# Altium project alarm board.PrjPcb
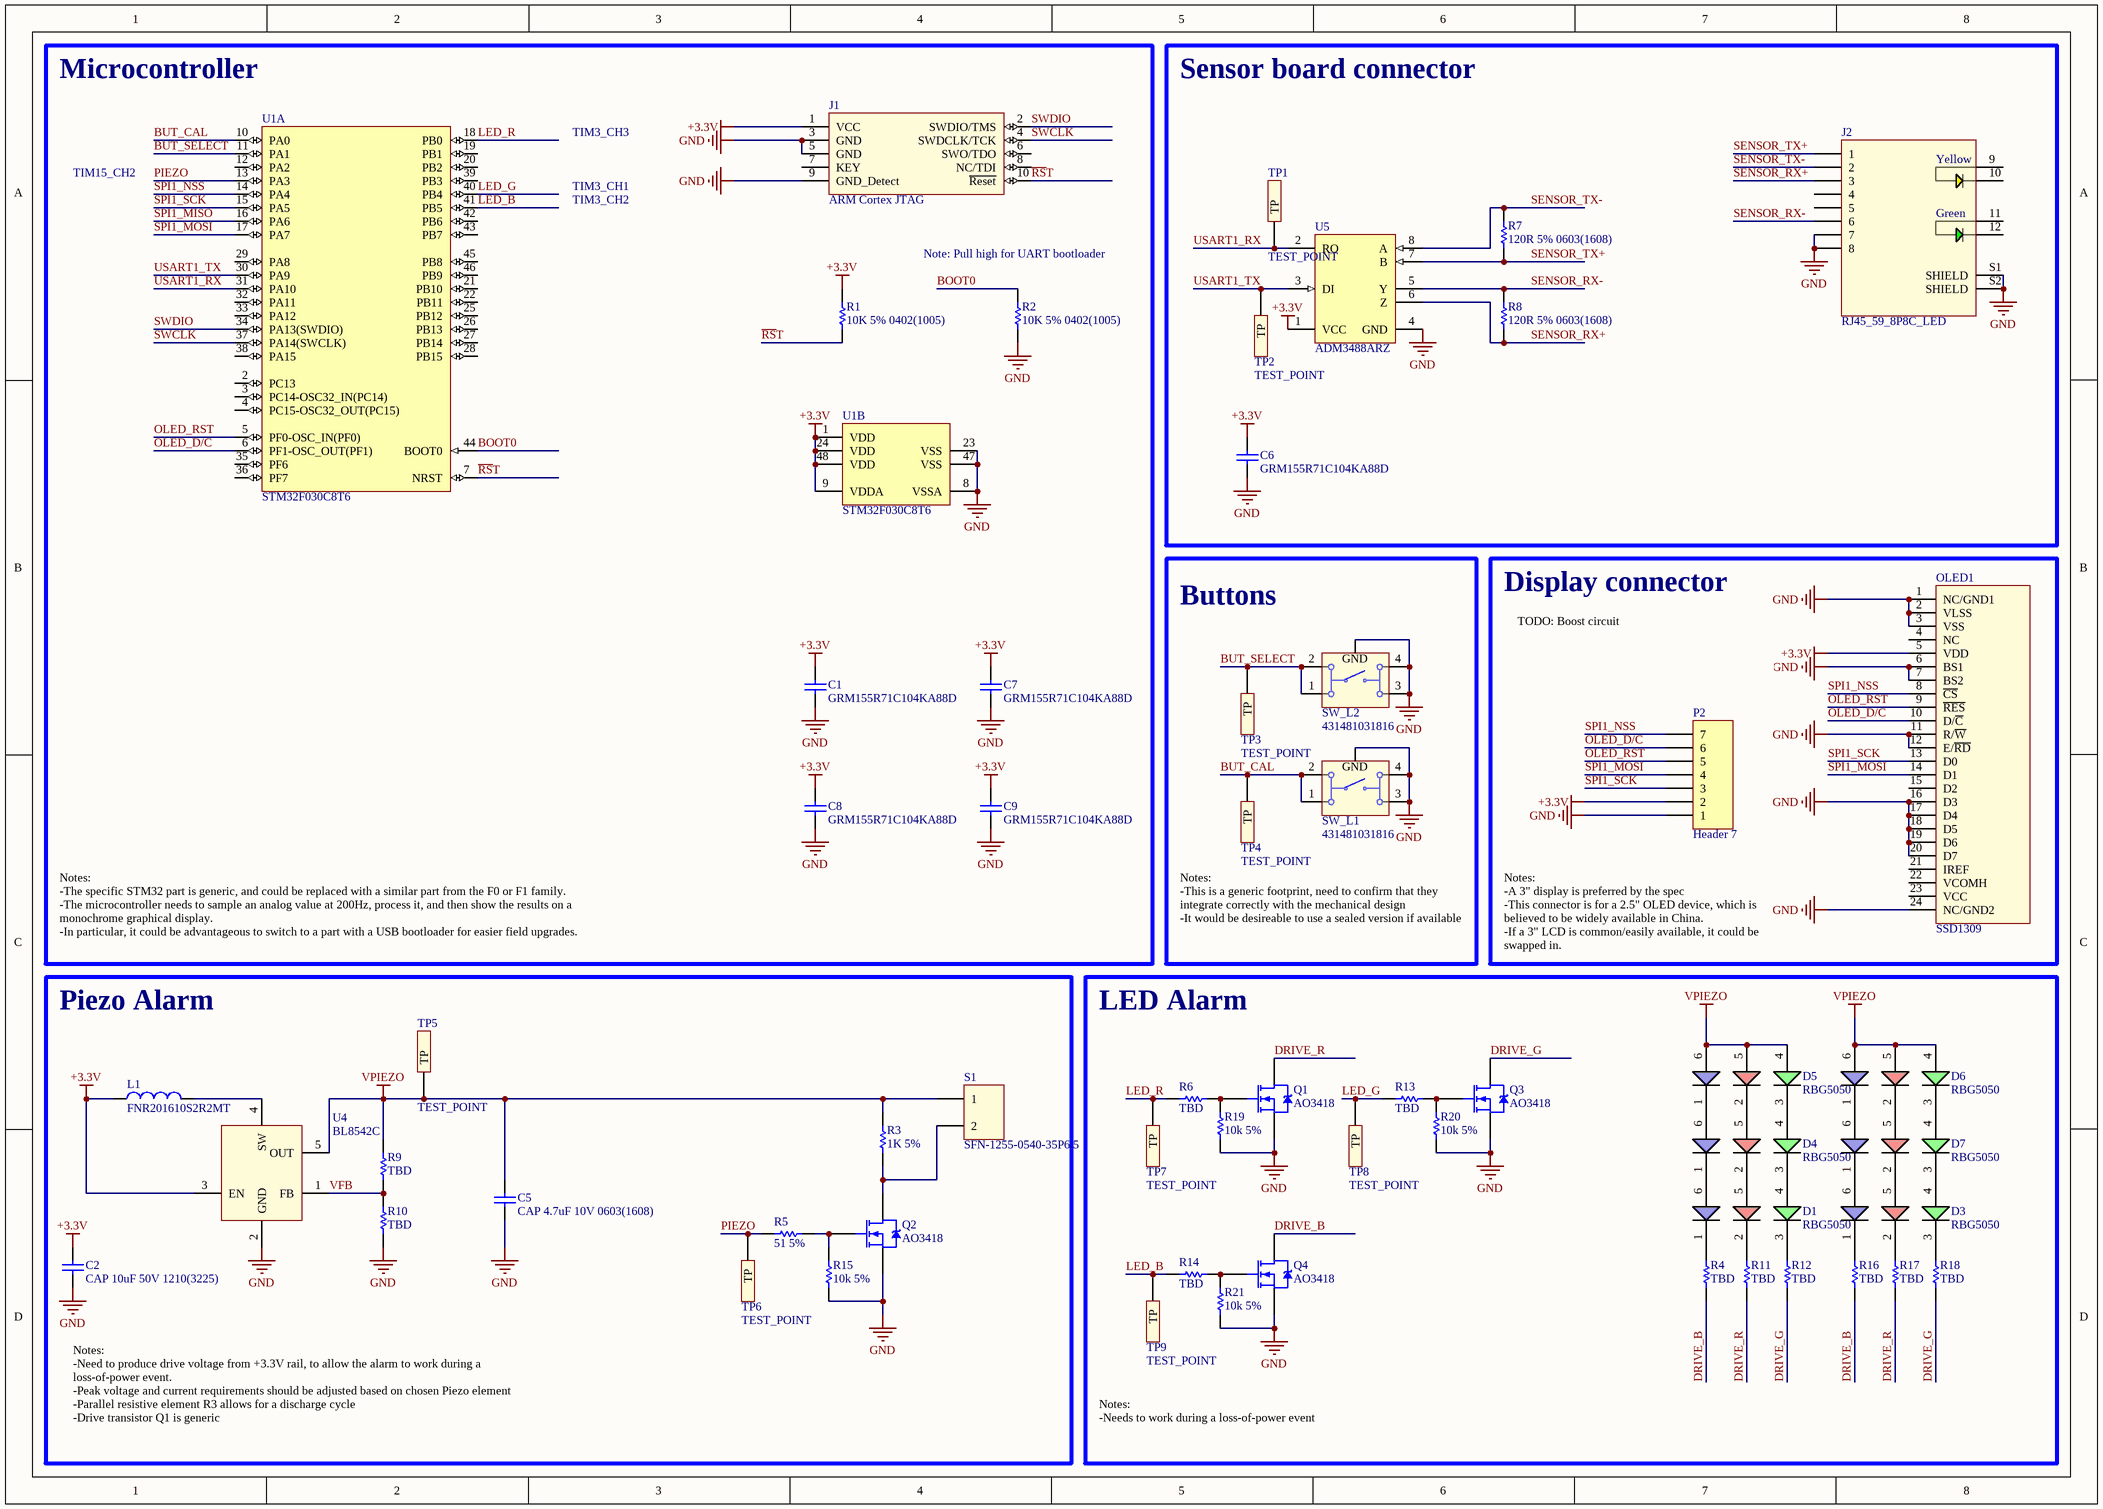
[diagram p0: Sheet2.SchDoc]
2 sheets, 68 parts. Net scope: global (net labels, ports and power ports of the same name join across sheets).
Board file: PCB2.PcbDoc
Sheets:
  Sheet2.SchDoc
  power.SchDoc

## Sheet Sheet2.SchDoc: Alarm Board
size A3

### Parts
C1  GRM155R71C104KA88D  [CAPC1005X55X25ML05T10]
C2  CAP 10uF 50V 1210(3225)  [CAPC1210(3225)190_N]
C5  CAP 4.7uF 10V 0603(1608)  [CAPC0603(1608)55_L]
C6  GRM155R71C104KA88D  [CAPC1005X55X25ML05T10]
C7  GRM155R71C104KA88D  [CAPC1005X55X25ML05T10]
C8  GRM155R71C104KA88D  [CAPC1005X55X25ML05T10]
C9  GRM155R71C104KA88D  [CAPC1005X55X25ML05T10]
D1  RBG5050  [5050RGB]
D3  RBG5050  [5050RGB]
D4  RBG5050  [5050RGB]
D5  RBG5050  [5050RGB]
D6  RBG5050  [5050RGB]
D7  RBG5050  [5050RGB]
J1  ARM Cortex JTAG  [1.27mm 2x5 SMD Header]
J2  RJ45_59_8P8C_LED  [RJ45_59_8P8C_LED]
L1  FNR201610S2R2MT  [FNR201610S]
OLED1  SSD1309
P2  Header 7  [HDR1X7]
Q1  AO3418  [SOT95P280X125-3N]
Q2  AO3418  [SOT95P280X125-3N]
Q3  AO3418  [SOT95P280X125-3N]
Q4  AO3418  [SOT95P280X125-3N]
R1  10K 5% 0402(1005)  [RESC0402(1005)_N]
R2  10K 5% 0402(1005)  [RESC0402(1005)_N]
R3  1K 5%  [RESC0402(1005)_N]
R4  TBD  [RESC0402(1005)_N]
R5  51 5%  [RESC0402(1005)_N]
R6  TBD  [RESC0402(1005)_N]
R7  120R 5% 0603(1608)  [RESC0603(1608)_L]
R8  120R 5% 0603(1608)  [RESC0603(1608)_L]
R9  TBD  [RESC0402(1005)_N]
R10  TBD  [RESC0402(1005)_N]
R11  TBD  [RESC0402(1005)_N]
R12  TBD  [RESC0402(1005)_N]
R13  TBD  [RESC0402(1005)_N]
R14  TBD  [RESC0402(1005)_N]
R15  10k 5%  [RESC0402(1005)_N]
R16  TBD  [RESC0402(1005)_N]
R17  TBD  [RESC0402(1005)_N]
R18  TBD  [RESC0402(1005)_N]
R19  10k 5%  [RESC0402(1005)_N]
R20  10k 5%  [RESC0402(1005)_N]
R21  10k 5%  [RESC0402(1005)_N]
S1  SFN-1255-0540-35P6.5  [SFN-1255-0540-35P6.5]
SW_L1  431481031816  [431481031816]
SW_L2  431481031816  [431481031816]
TP1  TEST_POINT  [TP-SMD-1mm]  (no BOM)
TP2  TEST_POINT  [TP-SMD-1mm]  (no BOM)
TP3  TEST_POINT  [TP-SMD-1mm]  (no BOM)
TP4  TEST_POINT  [TP-SMD-1mm]  (no BOM)
TP5  TEST_POINT  [TP-SMD-1mm]  (no BOM)
TP6  TEST_POINT  [TP-SMD-1mm]  (no BOM)
TP7  TEST_POINT  [TP-SMD-1mm]  (no BOM)
TP8  TEST_POINT  [TP-SMD-1mm]  (no BOM)
TP9  TEST_POINT  [TP-SMD-1mm]  (no BOM)
U1  STM32F030C8T6  [STM-LQFP48_M]  (parts A,B of 2)
U4  BL8542C  [SOT95P280X130-5N]
U5  ADM3488ARZ  [ADI-R-8_L]

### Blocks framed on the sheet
Microcontroller: C1 C7-C9 J1 R1 R2 U1
Sensor board connector: C6 J2 R7 R8 TP1 TP2 U5
Buttons: SW_L1 SW_L2 TP3 TP4
Display connector: OLED1 P2
Piezo Alarm: C2 C5 L1 Q2 R3 R5 R9 R10 R15 S1 TP5 TP6 U4
LED Alarm: D1 D3-D7 Q1 Q3 Q4 R4 R6 R11-R14 R16-R21 TP7-TP9

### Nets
+3.3V: C1.2 C2.2 C6.2 C7.2 C8.2 C9.2 J1.1(VCC) L1.1 OLED1.5(VDD) P2.2 R1.1 U1.1(VDD) U1.9(VDDA) U1.24(VDD) U1.48(VDD) U4.3(EN) U5.1(VCC)
GND: C1.1 C2.1 C5.1 C6.1 C7.1 C8.1 C9.1 J1.3(GND) J1.5(GND) J1.9(GND_Detect) J2.7 J2.8 J2.S1(SHIELD) J2.S2(SHIELD) OLED1.1(NC/GND1) OLED1.2(VLSS) OLED1.3(VSS) OLED1.6(BS1) OLED1.7(BS2) OLED1.11(R/~{W}) OLED1.12(E/~{RD}) OLED1.16(D3) OLED1.17(D4) OLED1.18(D5) OLED1.19(D6) OLED1.20(D7) OLED1.24(NC/GND2) P2.1 Q1.2(SOURCE) Q2.2(SOURCE) Q3.2(SOURCE) Q4.2(SOURCE) R2.2 R10.1 R15.1 R19.1 R20.1 R21.1 SW_L1.3 SW_L1.4 SW_L1.5 SW_L2.3 SW_L2.4 SW_L2.5 U1.8(VSSA) U1.23(VSS) U1.47(VSS) U4.2(GND) U5.4(GND)
VPIEZO: C5.2 D5.4 D5.5 D5.6 D6.4 D6.5 D6.6 R3.2 R9.2 S1.1 TP5.1(TP) U4.5(OUT)
~{RS}T: J1.10(~{Reset}) R1.2 U1.7(NRST)
BOOT0: R2.1 U1.44(BOOT0)
BUT_CAL: SW_L1.1 SW_L1.2 TP4.1(TP) U1.10(PA0)
BUT_SELECT: SW_L2.1 SW_L2.2 TP3.1(TP) U1.11(PA1)
DRIVE_B: Q4.3(DRAIN) R4.1 R16.1
DRIVE_G: Q3.3(DRAIN) R12.1 R18.1
DRIVE_R: Q1.3(DRAIN) R11.1 R17.1
LED_B: R14.1 TP9.1(TP) U1.41(PB5)
LED_G: R13.1 TP8.1(TP) U1.40(PB4)
LED_R: R6.1 TP7.1(TP) U1.18(PB0)
OLED_D/C: OLED1.10(D/~{C}) P2.6 U1.6(PF1-OSC_OUT(PF1))
OLED_RST: OLED1.9(~{RES}) P2.5 U1.5(PF0-OSC_IN(PF0))
PIEZO: R5.1 TP6.1(TP) U1.13(PA3)
SENSOR_RX+: J2.3 R8.1 U5.6(Z)
SENSOR_RX-: J2.6 R8.2 U5.5(Y)
SENSOR_TX+: J2.1 R7.1 U5.7(B)
SENSOR_TX-: J2.2 R7.2 U5.8(A)
SPI1_MISO: U1.16(PA6)
SPI1_MOSI: OLED1.14(D1) P2.4 U1.17(PA7)
SPI1_NSS: OLED1.8(~{CS}) P2.7 U1.14(PA4)
SPI1_SCK: OLED1.13(D0) P2.3 U1.15(PA5)
SWCLK: J1.4(SWDCLK/TCK) U1.37(PA14(SWCLK))
SWDIO: J1.2(SWDIO/TMS) U1.34(PA13(SWDIO))
USART1_RX: TP1.1(TP) U1.31(PA10) U5.2(RO)
USART1_TX: TP2.1(TP) U1.30(PA9) U5.3(DI)
VFB: R9.1 R10.2 U4.1(FB)
NetD1_1: D1.1 R4.2
NetD1_2: D1.2 R11.2
NetD1_3: D1.3 R12.2
NetD1_4: D1.4 D4.3
NetD1_5: D1.5 D4.2
NetD1_6: D1.6 D4.1
NetD3_1: D3.1 R16.2
NetD3_2: D3.2 R17.2
NetD3_3: D3.3 R18.2
NetD3_4: D3.4 D7.3
NetD3_5: D3.5 D7.2
NetD3_6: D3.6 D7.1
NetD4_4: D4.4 D5.3
NetD4_5: D4.5 D5.2
NetD4_6: D4.6 D5.1
NetD6_1: D6.1 D7.6
NetD6_2: D6.2 D7.5
NetD6_3: D6.3 D7.4
NetL1_2: L1.2 U4.4(SW)
NetQ1_1: Q1.1(GATE) R6.2 R19.2
NetQ2_1: Q2.1(GATE) R5.2 R15.2
NetQ2_3: Q2.3(DRAIN) R3.1 S1.2
NetQ3_1: Q3.1(GATE) R13.2 R20.2
NetQ4_1: Q4.1(GATE) R14.2 R21.2

Not connected (* = marked no-connect by the designer): J1 6(SWO/TDO) 7(KEY) 8(NC/TDI); J2 4 5 9(Yellow_Anode) 10(Yellow_Cathode) 11(Green_Anode) 12(Green_Cathode); OLED1 4(NC) 15(D2) 21(IREF) 22(VCOMH) 23(VCC); U1 2(PC13) 3(PC14-OSC32_IN(PC14)) 4(PC15-OSC32_OUT(PC15)) 12(PA2) 19(PB1) 20(PB2) 21(PB10) 22(PB11) 25(PB12) 26(PB13) 27(PB14) 28(PB15) 29(PA8) 32(PA11) 33(PA12) 35(PF6) 36(PF7) 38(PA15) 39(PB3) 42(PB6) 43(PB7) 45(PB8) 46(PB9)

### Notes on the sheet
- TIM15_CH2
- TIM3_CH3
- TIM3_CH1
- TIM3_CH2
- (near R2) Note: Pull high for UART bootloader
- (near P2) TODO: Boost circuit
- Notes:
  -The specific STM32 part is generic, and could be replaced with a similar part from the F0 or F1 family.
  -The microcontroller needs to sample an analog value at 200Hz, process it, and then show the results on a monochrome graphical display.
  -In particular, it could be advantageous to switch to a part with a USB bootloader for easier field upgrades.
- Notes:
  -This is a generic footprint, need to confirm that they integrate correctly with the mechanical design
  -It would be desireable to use a sealed version if available
- Notes:
  -A 3" display is preferred by the spec
  -This connector is for a 2.5" OLED device, which is believed to be widely available in China.
  -If a 3" LCD is common/easily available, it could be swapped in.
- Notes:
  -Need to produce drive voltage from +3.3V rail, to allow the alarm to work during a loss-of-power event.
  -Peak voltage and current requirements should be adjusted based on chosen Piezo element
  -Parallel resistive element R3 allows for a discharge cycle
  -Drive transistor Q1 is generic
- Notes:
  -Needs to work during a loss-of-power event

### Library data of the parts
C1 C6-C9 = CMP-2100-03641-1: Chip Capacitor, 0.1 uF, +/- 10%, 16 V, -55 to 125 degC, 0402 (1005 Metric), RoHS, Tape and Reel; Manufacturer: Murata; Material: Ceramic; Insulation Resistance: 10GR; Voltage: 16V; Dielectric: X7R; Capacitance: 100nF
C2 = CMP-1038-02238-1: CAP 10uF 50V -20% to +80% 1210 (3225 Metric) Thickness 1.9mm SMD; Case-Metric: 3225; Case-EIA: 1210
C5 = CMP-1035-02784-1: CAP 4.7uF 10V ±10% 0603 (1608 Metric) Thickness 0.55mm SMD; Case-Metric: 1608; Tolerance: Â±10%; Case-EIA: 0603
D1 D3-D7 = RBG5050: Generic RGB LED in 5050 package. Note that several variants exist, so check the pinout!; PartNumber: Unknown/Generic
J1 = ARM Cortex JTAG: Arm Cortex 10-pin JTAG connector; Manufacturer: Unknown/Generic
J2 = RJ45_59_8P8C_LED: Generic RJ49 jack with LED and without magnetics; Manufacturer: Unknown/Generic
L1 = FNR201610S2R2MT: Wire Wound SMD Power Inductors 2.0×1.6×1.0 2.2uH
OLED1 = SSD1309: 2.4" OLED display, 24-pin connector, SSD1309 driver IC
P2 = Header 7: Header, 7-Pin
Q1-Q4 = AO3418: 30V N-Channel MOSFET; Manufacturer: Alpha & Omega
R1-R6 R9-R21 = CMP-1011-00098-1: 10K 0.063W 5% 0402 (1005 Metric)  SMD; Case-Metric: 1005; Value: 10000.00 Ohm; Case-EIA: 0402
R7 R8 = CMP-1012-00052-1: 120R 0.1W 5% 0603 (1608 Metric)  SMD; Case-EIA: 0603; Value: 120.00 Ohm; Case-Metric: 1608
S1 = SFN-1255-0540-35P6.5: Piezo Buzzer, 4KHz; Manufacturer: S&S
SW_L1 SW_L2 = CMP-1457-00011-1: WS-TASV SMD Tact Switch 6X6 mm with ground terminal; Manufacturer: Wuerth Elektronik; NoPins: 04
TP1-TP9 = TEST_POINT: Test point
U1 = CMP-0304-00024-2: ARM Cortex-M0 32-bit MCU, 64 KB Flash, 8 KB Internal RAM, 39 I/Os, 48-pin LQFP, -40 to 85 degC, Tray; FLASH Size (Prog) (kB): 64; I/Os (High Current): 39; Operating Frequency(F) (Processor speed) (MHz): 48; Supply Voltage(Vcc) min (V): 2.4; Internal RAM Size (kB): 8
U4 = BL8542C: 0.85V startup, 1MHz, 300mA Iout,  Synchronous Boost Converter (adjustable output); Manufacturer: Belling
U5 = CMP-0535-00058-1: 3.3 V Slew Rate Limited, Full-Duplex, RS-485/RS-422 Transceivers, 3 to 3.6 V, -40 to 85 degC, 8-Pin SOIC (R-8), RoHS, Tube; Manufacturer: Analog Devices; Guaranteed Data Rate: 0.25 Mbps; Receiver Hysteresis: 50 mV; Number of Drivers: 1; Duplex: Full

## Sheet power.SchDoc: Power Supply
size A4
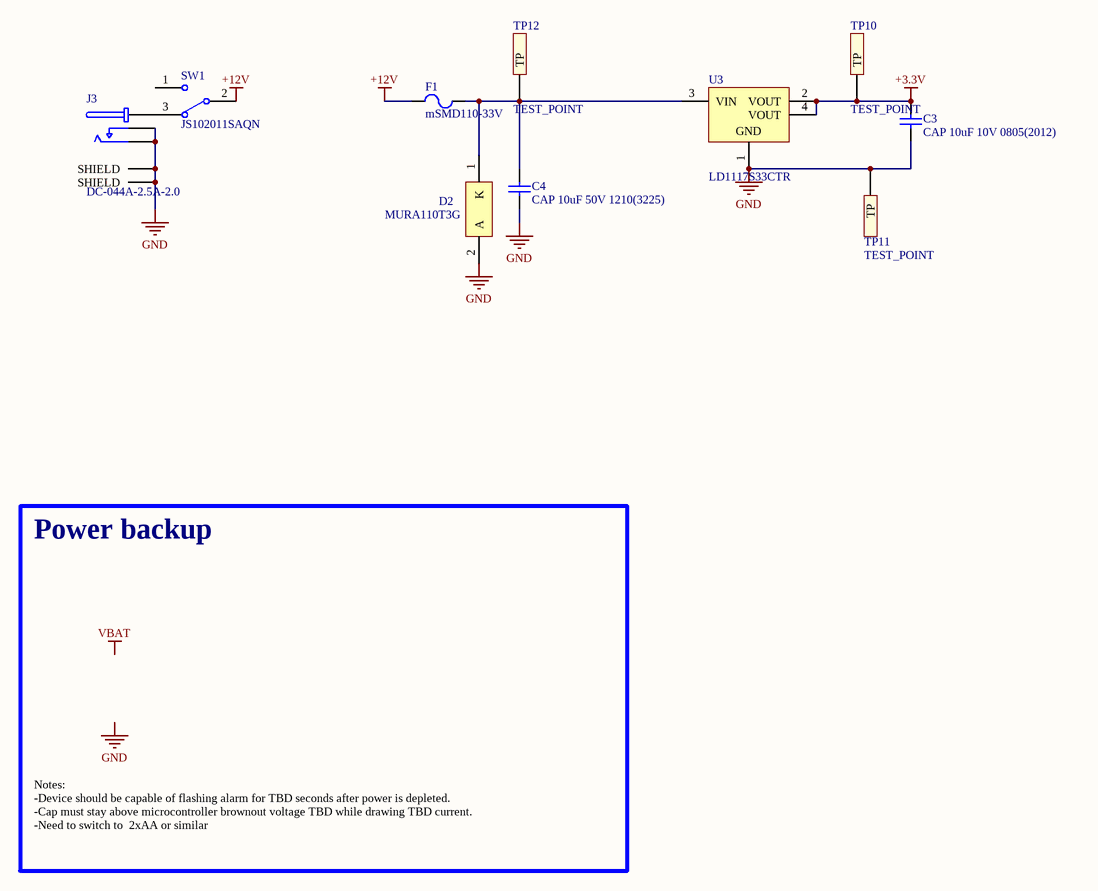
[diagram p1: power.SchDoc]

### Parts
C3  CAP 10uF 10V 0805(2012)  [CAPC0805(2012)145_N]
C4  CAP 10uF 50V 1210(3225)  [CAPC1210(3225)190_N]
D2  MURA110T3G  [ONSC-SMA-2-403D-02_V]
F1  mSMD110-33V  [SEAANDLAND_1812]
J3  DC-044A-2.5A-2.0  [DC-044A-2.5A-2.0]
SW1  JS102011SAQN  [CKCP-JS102011SAQN-3_V]
TP10  TEST_POINT  [TP-SMD-1mm]  (no BOM)
TP11  TEST_POINT  [TP-SMD-1mm]  (no BOM)
TP12  TEST_POINT  [TP-SMD-1mm]  (no BOM)
U3  LD1117S33CTR  [SOT-223_N]

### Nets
+3.3V: C3.2 TP10.1(TP) U3.2(VOUT) U3.4(VOUT)
+12V: F1.1 SW1.2
GND: C3.1 C4.1 D2.2(A) J3.2 J3.3 J3.4(SHIELD) J3.5(SHIELD) TP11.1(TP) U3.1(GND)
NetC4_2: C4.2 D2.1(K) F1.2 TP12.1(TP) U3.3(VIN)
NetJ3_1: J3.1 SW1.3

Not connected (* = marked no-connect by the designer): SW1 1

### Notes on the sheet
- Power backup
- Notes:
  -Device should be capable of flashing alarm for TBD seconds after power is depleted.
  -Cap must stay above microcontroller brownout voltage TBD while drawing TBD current.
  -Need to switch to  2xAA or similar
- Labels drawn without touching a wire or pin: GND, VBAT

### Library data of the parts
C3 = CMP-1036-04922-1: CAP 10uF 10V ±10% 0805 (2012 Metric) Thickness 1.45mm SMD; Tolerance: Â±10%; Case-EIA: 0805; Case-Metric: 2012
C4 = CMP-1038-02238-1: as C2 on sheet Sheet2
D2 = CMP-0902-00293-1: Surface Mount Ultrafast Power Rectifier, 2-Pin SMA, Pb-Free, Tape and Reel; Manufacturer: On Semiconductor; IFSM Max (A): 50
F1 = mSMD110-33V: Surface Mount Fuses 33V 100A 1.1A 2.2A 1812 RoHS; Manufacturer: Sea & Land Electronic Corp
J3 = DC-044A-2.5A-2.0: DC Jack, 6mm OD, 2mm ID; Manufacturer: XKB
SW1 = CMP-2000-06501-1: Sub-Miniature Slide Switch, SPDT, -40 to 85 degC, 3-Pin SMD, RoHS, Tape and Reel; Manufacturer: C&K Components; Electrical Life: 15000Cycles; Actuator Color: Black; Body Orientation: RightAngle; Minimum Insulation Resistance: 100MOhm; Contact Rating @ Voltage: 0.3@6VDCA; Actuator Style: SideSlide; Maximum DC Voltage Rating: 6V; COO: US; Actuator Material: Nylon4/6; Dielectric Strength: 500VAC; Maximum Contact Resistance: 70mOhm
TP10-TP12 = TEST_POINT: Test point
U3 = CMP-0244-00307-1: Fixed Low Drop Positive Voltage Regulator, 3.3V, 4-Pin SOT-223, Tape and Reel

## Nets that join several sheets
+3.3V: Sheet2 (17 pins), power (C3.2 TP10.1 U3.2 U3.4)
GND: Sheet2 (49 pins), power (9 pins)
